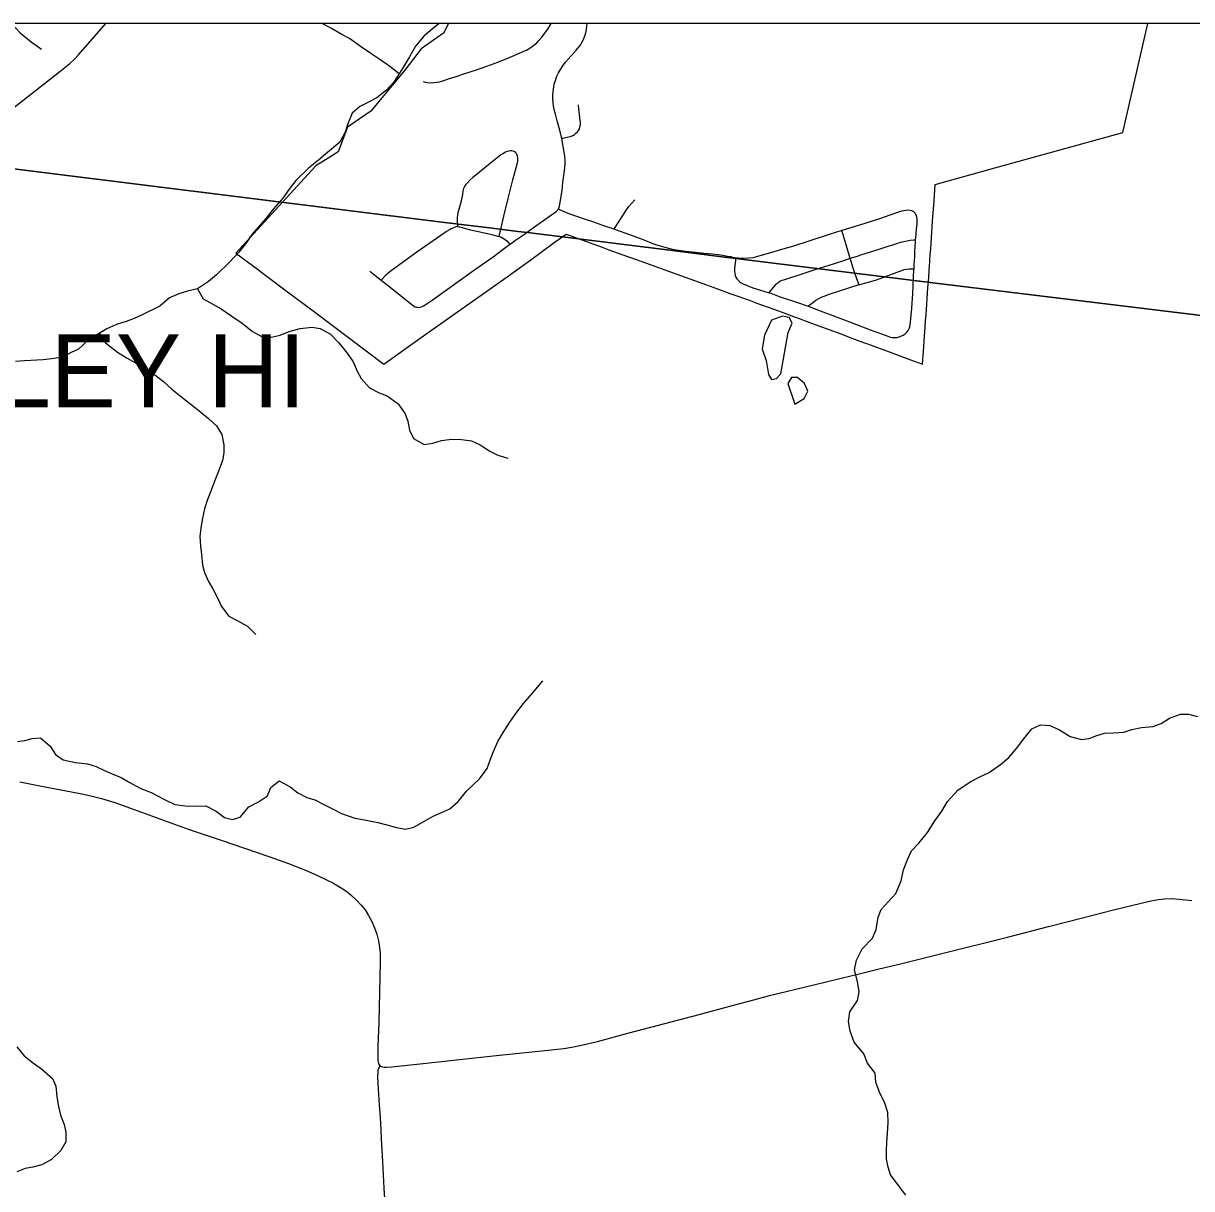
# Model space of a CAD drawing. Extents: x 0 to 1101, y 0 to 440.
# Drawn here: x 844.169 to 845.685, y 380.394 to 381.906 of the extents above; entities that cross this region are included whole.
import ezdxf

# ---------------------------------------------------------------- set-up
doc = ezdxf.new("R2010")
doc.units = 0
for name, color, linetype in [('GM_X_City_Street', 7, 'Continuous'), ('GM_X_Corporation', 7, 'Continuous'), ('GM_X_Corporation_Text', 7, 'Continuous'), ('GM_X_County_Road', 7, 'Continuous'), ('GM_X_Major_River', 7, 'Continuous'), ('GM_X_Minor_Lake', 7, 'Continuous'), ('GM_X_Minor_River', 7, 'Continuous'), ('SH_Cut_Line', 7, 'Continuous')]:
    doc.layers.add(name, color=color, linetype=linetype)

msp = doc.modelspace()

# ---------------------------------------------------------------- linework, layer by layer
at = {"layer": 'GM_X_City_Street'}
for points in [[(844.6879, 381.8304), (844.6906, 381.8296), (844.6933, 381.8292), (844.6975, 381.8289), (844.7017, 381.8291), (844.7054, 381.8295), (844.7089, 381.8302), (844.7131, 381.8315), (844.722, 381.8343), (844.7292, 381.8366), (844.7419, 381.8407), (844.7569, 381.8455), (844.7705, 381.8502), (844.7848, 381.8557), (844.8006, 381.8618), (844.8135, 381.8675), (844.8191, 381.8701), (844.8217, 381.8712), (844.824, 381.8725), (844.8279, 381.875), (844.8315, 381.8776), (844.835, 381.8808), (844.8383, 381.8841), (844.8417, 381.8881), (844.8453, 381.8927), (844.8493, 381.8984), (844.8526, 381.9037), (844.8537, 381.9059)], [(844.7784, 381.603), (844.7898, 381.6117), (844.7969, 381.6169), (844.8005, 381.6194), (844.8077, 381.6245), (844.8206, 381.6332), (844.8215, 381.6339), (844.8353, 381.6438), (844.8529, 381.6564), (844.8561, 381.6587), (844.8581, 381.6602), (844.8607, 381.6622), (844.8622, 381.6635), (844.8633, 381.6649), (844.8635, 381.6651), (844.8641, 381.6666), (844.8646, 381.6686), (844.865, 381.6714), (844.8679, 381.6892), (844.8689, 381.6993), (844.8705, 381.7117), (844.8714, 381.7189), (844.8719, 381.7238), (844.8719, 381.7284), (844.8715, 381.7335), (844.8708, 381.7388), (844.8677, 381.7563), (844.8676, 381.7566), (844.865, 381.7672), (844.8617, 381.7796), (844.8596, 381.788), (844.8579, 381.7939), (844.8568, 381.7989), (844.8562, 381.8024), (844.8558, 381.8078), (844.856, 381.8133), (844.8567, 381.8207), (844.8579, 381.8268), (844.8593, 381.8319), (844.8609, 381.8364), (844.8634, 381.8416), (844.8658, 381.846), (844.8689, 381.8509), (844.8722, 381.8554), (844.8758, 381.8596), (844.8796, 381.8637), (844.8862, 381.8709), (844.8889, 381.8741), (844.8917, 381.8778), (844.8937, 381.881), (844.8954, 381.8841), (844.8971, 381.8883), (844.8987, 381.8937), (844.8996, 381.8982), (844.9002, 381.9024), (844.9005, 381.9059)], [(844.8676, 381.7566), (844.869, 381.757), (844.8761, 381.7585), (844.8791, 381.7592), (844.8819, 381.7605), (844.8839, 381.7617), (844.886, 381.7633), (844.8879, 381.7651), (844.8893, 381.7669), (844.8904, 381.769), (844.8912, 381.7714), (844.8917, 381.7744), (844.8917, 381.7773), (844.8912, 381.7827), (844.8905, 381.7886), (844.8899, 381.7946), (844.8893, 381.8003)], [(844.7861, 381.6294), (844.7862, 381.6298), (844.7878, 381.6353), (844.7884, 381.6382), (844.7923, 381.6559), (844.7979, 381.6788), (844.804, 381.7029), (844.8101, 381.725), (844.8104, 381.7266), (844.8107, 381.7291), (844.8106, 381.7309), (844.8103, 381.7336), (844.8094, 381.7359), (844.8087, 381.7371), (844.8075, 381.7385), (844.8057, 381.7396), (844.804, 381.7402), (844.8022, 381.7404), (844.8006, 381.7404), (844.7987, 381.7401), (844.7968, 381.7396), (844.7944, 381.7387), (844.7909, 381.7367), (844.7884, 381.7351), (844.7856, 381.7328), (844.7772, 381.726), (844.7559, 381.7089), (844.7522, 381.7059), (844.7484, 381.7024), (844.7447, 381.6986), (844.7427, 381.6963), (844.7413, 381.694), (844.7402, 381.6914), (844.7394, 381.6883), (844.7389, 381.6844), (844.7382, 381.6812), (844.7376, 381.6783), (844.7369, 381.6751), (844.7336, 381.6632), (844.7329, 381.6599), (844.7323, 381.6569), (844.732, 381.6545), (844.7319, 381.651), (844.7318, 381.648), (844.7322, 381.6424), (844.735, 381.6418), (844.7379, 381.6411), (844.7426, 381.6399), (844.7493, 381.6381), (844.7634, 381.6349), (844.7769, 381.6318), (844.7861, 381.6294), (844.7883, 381.6287), (844.7906, 381.6276), (844.7928, 381.6263), (844.7944, 381.6251), (844.7961, 381.6237), (844.7995, 381.6203), (844.8005, 381.6194)], [(844.8633, 381.6649), (844.8648, 381.6642), (844.8754, 381.6598), (844.8867, 381.6555), (844.8978, 381.6518), (844.9073, 381.6486), (844.9218, 381.6437), (844.9338, 381.6395), (844.9358, 381.6388), (844.9556, 381.6318), (844.9717, 381.6257), (844.9739, 381.6248), (844.9864, 381.62), (844.9903, 381.6187), (844.9952, 381.617), (845.0013, 381.6153), (845.006, 381.614), (845.0116, 381.6128), (845.0159, 381.612), (845.028, 381.6103), (845.0411, 381.6089), (845.0517, 381.6078), (845.0631, 381.6066), (845.0705, 381.6058), (845.0767, 381.6049)], [(844.9358, 381.6388), (844.9362, 381.6395), (844.9485, 381.6593), (844.95, 381.6615), (844.9516, 381.6639), (844.9548, 381.6681), (844.9584, 381.6727), (844.9623, 381.677)], [(845.0767, 381.6049), (845.0828, 381.6039), (845.0863, 381.6032), (845.0907, 381.6022), (845.0936, 381.6015), (845.0922, 381.5918), (845.0918, 381.5876), (845.0918, 381.5844), (845.0921, 381.5817), (845.0926, 381.5789), (845.0935, 381.5766), (845.0949, 381.5744), (845.0963, 381.5725), (845.0982, 381.5707), (845.1002, 381.5693), (845.1029, 381.5678), (845.1156, 381.5628), (845.1256, 381.5596), (845.1366, 381.5564), (845.1387, 381.5558), (845.1497, 381.5516), (845.1735, 381.5435), (845.1858, 381.5392), (845.1871, 381.5388), (845.2027, 381.5329), (845.2282, 381.5232), (845.2498, 381.5153), (845.2678, 381.5084), (845.2826, 381.5028), (845.2905, 381.5), (845.2926, 381.4992), (845.294, 381.4988), (845.2961, 381.4983), (845.2981, 381.4981), (845.3005, 381.4981), (845.3029, 381.4984), (845.3054, 381.4991), (845.3076, 381.4999), (845.3106, 381.5014), (845.313, 381.5031), (845.3153, 381.5052), (845.3169, 381.5075), (845.3183, 381.51), (845.3191, 381.5122), (845.3196, 381.5149), (845.3201, 381.5183), (845.3219, 381.5361), (845.3229, 381.5553), (845.3245, 381.5863), (845.3246, 381.5876), (845.325, 381.594), (845.3251, 381.5972), (845.3255, 381.6036), (845.3258, 381.6098), (845.3261, 381.6165), (845.3264, 381.6221), (845.3266, 381.6248), (845.3269, 381.6276), (845.328, 381.6387), (845.3284, 381.6428), (845.3286, 381.6459), (845.3288, 381.6495), (845.3287, 381.6523), (845.3283, 381.6546), (845.3277, 381.6565), (845.3269, 381.658), (845.326, 381.6595), (845.3245, 381.6611), (845.3227, 381.6621), (845.32, 381.663), (845.3168, 381.6634), (845.314, 381.6632), (845.3112, 381.6627), (845.3084, 381.662), (845.3021, 381.66), (845.2784, 381.6519), (845.2526, 381.6434), (845.2311, 381.637), (845.2145, 381.6321), (845.1867, 381.6229), (845.1668, 381.6165), (845.1498, 381.6114), (845.1413, 381.6089), (845.1217, 381.6033), (845.1158, 381.6018), (845.1101, 381.6011), (845.104, 381.6009), (845.0998, 381.6008), (845.0964, 381.601), (845.0936, 381.6015)], [(844.7322, 381.6424), (844.7301, 381.6418), (844.7264, 381.6402), (844.724, 381.6391), (844.7218, 381.6378), (844.7189, 381.6361), (844.7161, 381.6344), (844.6797, 381.609), (844.6479, 381.5862), (844.6444, 381.5836), (844.6413, 381.5809), (844.6386, 381.5781), (844.6342, 381.5735), (844.6334, 381.5726), (844.6408, 381.5667), (844.6708, 381.5426), (844.6733, 381.5406), (844.6752, 381.5393), (844.6772, 381.5382), (844.6789, 381.5377), (844.6805, 381.5374), (844.6826, 381.5373), (844.6842, 381.5377), (844.6864, 381.5383), (844.6883, 381.5394), (844.6904, 381.5408), (844.6992, 381.5469), (844.7561, 381.5872), (844.7784, 381.603)], [(845.2534, 381.5669), (845.2531, 381.5676), (845.2498, 381.5757), (845.2458, 381.5881), (845.2418, 381.601), (845.2408, 381.6038), (845.2367, 381.6184), (845.2315, 381.6357), (845.2311, 381.637)], [(845.1366, 381.5564), (845.1377, 381.5576), (845.1436, 381.5648), (845.1456, 381.5673), (845.1466, 381.5684), (845.1478, 381.5693), (845.1494, 381.5704), (845.1515, 381.5716), (845.1537, 381.5725), (845.1569, 381.5737), (845.1797, 381.5809), (845.1978, 381.5868), (845.2203, 381.594), (845.2361, 381.5992), (845.2418, 381.601), (845.2512, 381.6039), (845.2558, 381.6054), (845.2805, 381.6131), (845.2912, 381.6166), (845.2985, 381.6191), (845.3022, 381.6203), (845.3072, 381.6218), (845.3115, 381.6229), (845.3157, 381.6238), (845.3198, 381.6244), (845.3245, 381.6248), (845.3266, 381.6248)], [(844.6187, 381.5842), (844.6252, 381.579), (844.6334, 381.5726)], [(845.1871, 381.5388), (845.1873, 381.539), (845.1932, 381.5438), (845.1974, 381.5467), (845.2012, 381.5488), (845.2056, 381.551), (845.2094, 381.5524), (845.2146, 381.5543), (845.2534, 381.5669), (845.2544, 381.5672), (845.2685, 381.571), (845.2759, 381.5731), (845.284, 381.5759), (845.291, 381.5786), (845.3061, 381.5843), (845.309, 381.5853), (845.312, 381.5863), (845.3149, 381.5869), (845.3182, 381.5873), (845.3236, 381.5875), (845.3246, 381.5876)]]:
    msp.add_lwpolyline(points, dxfattribs=at)
at = {"layer": 'GM_X_Corporation'}
msp.add_lwpolyline([(845.6282, 381.9059), (844.7207, 381.9059), (844.7139, 381.8932), (844.6853, 381.873), (844.6695, 381.8527), (844.6635, 381.8449), (844.6199, 381.792), (844.6197, 381.7918), (844.5897, 381.7713), (844.5775, 381.7392), (844.5702, 381.7346), (844.5484, 381.7209), (844.5053, 381.674), (844.4448, 381.6078), (844.466, 381.5919), (844.5082, 381.5603), (844.5467, 381.5314), (844.6368, 381.4638), (844.684, 381.4972), (844.7969, 381.5771), (844.8122, 381.5882), (844.8274, 381.5992), (844.8427, 381.6103), (844.8579, 381.6214), (844.8732, 381.6324), (844.8852, 381.628), (844.903, 381.6215), (844.9199, 381.6153), (844.9288, 381.612), (844.9467, 381.6056), (844.9641, 381.5993), (844.9821, 381.5928), (845.0059, 381.5842), (845.0231, 381.5781), (845.0396, 381.5721), (845.0552, 381.5665), (845.0698, 381.5613), (845.0869, 381.5551), (845.0975, 381.5513), (845.1048, 381.5487), (845.1121, 381.5461), (845.1184, 381.5438), (845.1194, 381.5434), (845.1267, 381.5408), (845.134, 381.5382), (845.1413, 381.5355), (845.1486, 381.5329), (845.1556, 381.5303), (845.1626, 381.5277), (845.1696, 381.5251), (845.1767, 381.5225), (845.1835, 381.5199), (845.1905, 381.5173), (845.1975, 381.5147), (845.2046, 381.5121), (845.2119, 381.5094), (845.219, 381.5068), (845.2262, 381.5041), (845.2332, 381.5015), (845.2404, 381.4988), (845.2474, 381.4962), (845.2544, 381.4936), (845.2618, 381.4909), (845.2689, 381.4882), (845.2759, 381.4856), (845.2832, 381.4829), (845.2902, 381.4803), (845.3214, 381.4687), (845.3358, 381.4637), (845.3369, 381.4801), (845.3383, 381.5001), (845.3392, 381.5127), (845.3397, 381.5199), (845.3402, 381.5271), (845.3403, 381.5283), (845.3407, 381.5343), (845.3412, 381.5414), (845.3417, 381.5486), (845.3422, 381.5558), (845.3427, 381.563), (845.3432, 381.5702), (845.3437, 381.5773), (845.3442, 381.5845), (845.3447, 381.5917), (845.345, 381.596), (845.3452, 381.5989), (845.3457, 381.6061), (845.3463, 381.6132), (845.3468, 381.6204), (845.3473, 381.6276), (845.3478, 381.6348), (845.3483, 381.642), (845.3488, 381.6491), (845.3506, 381.6757), (845.3521, 381.6969), (845.36, 381.6991), (845.4219, 381.7162), (845.5954, 381.7643)], close=True, dxfattribs=at)
at = {"layer": 'GM_X_County_Road'}
msp.add_lwpolyline([(847.9476, 381.9059), (842.3157, 381.9059), (843.023, 381.8481), (843.2462, 381.8298), (844.0658, 381.7282), (844.7118, 381.648), (844.7738, 381.6404), (844.8107, 381.6358), (844.8229, 381.6343), (845.008, 381.6114), (845.0655, 381.6042), (845.3492, 381.569), (845.7047, 381.5258), (845.7218, 381.5239), (845.8327, 381.5116), (846.7534, 381.4335), (846.7617, 381.4329), (846.7789, 381.4314), (846.8323, 381.427), (847.896, 381.3391), (847.9127, 381.5179)], close=True, dxfattribs=at)
for points in [[(844.0691, 381.7292), (844.1069, 381.7581), (844.1681, 381.8059), (844.2162, 381.8433), (844.2228, 381.8484), (844.2292, 381.8538), (844.2348, 381.8592), (844.2406, 381.865), (844.2644, 381.8921), (844.2761, 381.9059)], [(847.5335, 377.0456), (847.6089, 377.9284), (847.6897, 378.8763), (847.7828, 379.9871), (847.8653, 380.9722), (847.896, 381.3391), (846.8323, 381.427), (846.7789, 381.4314), (846.7617, 381.4329), (846.7534, 381.4335), (845.8327, 381.5116), (845.7218, 381.5239), (845.7047, 381.5258), (845.3492, 381.569), (845.0655, 381.6042), (845.008, 381.6114), (844.8229, 381.6343), (844.8107, 381.6358), (844.7738, 381.6404), (844.7118, 381.648), (844.0658, 381.7282)], [(844.1643, 380.9218), (844.1905, 380.9164), (844.2404, 380.9068), (844.2492, 380.9052), (844.2618, 380.9024), (844.2704, 380.9002), (844.2876, 380.8947), (844.3128, 380.8859), (844.3556, 380.87), (844.384, 380.86), (844.4257, 380.8459), (844.4873, 380.8247), (844.513, 380.8155), (844.5349, 380.8069), (844.5498, 380.8006), (844.5633, 380.7942), (844.5705, 380.7904), (844.5812, 380.7841), (844.5885, 380.7793), (844.5949, 380.7743), (844.6009, 380.7687), (844.6073, 380.7618), (844.6123, 380.7554), (844.617, 380.748), (844.6212, 380.7403), (844.6247, 380.7322), (844.6275, 380.724), (844.6297, 380.7155), (844.6312, 380.7068), (844.6319, 380.6993), (844.6321, 380.6875), (844.6304, 380.6098), (844.6291, 380.5781), (844.6288, 380.5651), (844.629, 380.5596), (844.6294, 380.5579), (844.6299, 380.5562), (844.6303, 380.5553), (844.6311, 380.5542), (844.6316, 380.5537), (844.6323, 380.5532), (844.6336, 380.5523), (844.6354, 380.5517), (844.6376, 380.5514), (844.6403, 380.5514), (844.6471, 380.5519), (844.6879, 380.5563), (844.7194, 380.5598), (844.7787, 380.5661), (844.8498, 380.5734), (844.8701, 380.5758), (844.883, 380.5779), (844.8969, 380.5807), (844.9138, 380.5848), (844.9551, 380.5961), (845.0458, 380.6197), (845.0903, 380.6318), (845.1167, 380.6389), (845.1371, 380.6442), (845.1945, 380.6582), (845.2301, 380.6669), (845.2516, 380.6722), (845.2776, 380.6785), (845.309, 380.6861), (845.3608, 380.6987), (845.4461, 380.7203), (845.4992, 380.7339), (845.5431, 380.7451), (845.5834, 380.7554), (845.6069, 380.7613), (845.6317, 380.7672), (845.6415, 380.7691), (845.6496, 380.77), (845.6584, 380.7702), (845.669, 380.7696), (845.6851, 380.7678)], [(844.6405, 380.3405), (844.6372, 380.3945), (844.6353, 380.4292), (844.6338, 380.4583), (844.6331, 380.4695), (844.6322, 380.4863), (844.631, 380.5024), (844.6293, 380.5302), (844.629, 380.5393), (844.6292, 380.545), (844.6294, 380.5471), (844.6297, 380.5487), (844.6309, 380.552), (844.6316, 380.5537)]]:
    msp.add_lwpolyline(points, dxfattribs=at)
at = {"layer": 'GM_X_Major_River'}
msp.add_lwpolyline([(844.7084, 381.9059), (844.6996, 381.8983), (844.6889, 381.8897), (844.6777, 381.8762), (844.6699, 381.8626), (844.6637, 381.8517), (844.6571, 381.8412), (844.6494, 381.8291), (844.6402, 381.819), (844.6275, 381.8093), (844.6161, 381.8034), (844.6054, 381.7982), (844.5954, 381.7893), (844.5899, 381.7753), (844.5864, 381.7647), (844.5794, 381.7519), (844.5636, 381.7381), (844.5521, 381.7284), (844.5391, 381.7179), (844.5226, 381.7018), (844.5137, 381.6909), (844.5056, 381.6789), (844.4937, 381.6654), (844.4837, 381.6526), (844.4659, 381.6324), (844.4571, 381.6196), (844.4486, 381.6091), (844.4366, 381.5959), (844.4197, 381.5795), (844.409, 381.5709), (844.3949, 381.5612), (844.3819, 381.5583), (844.3705, 381.5551), (844.3587, 381.5496), (844.3461, 381.5387), (844.3224, 381.5273), (844.3129, 381.5228), (844.3022, 381.5188), (844.29, 381.5152), (844.2774, 381.5093), (844.2641, 381.5019), (844.2534, 381.4952), (844.2407, 381.4832), (844.2312, 381.4788), (844.2201, 381.4729), (844.2057, 381.4704), (844.1947, 381.4691), (844.1704, 381.4679), (844.1586, 381.4673)], dxfattribs=at)
at = {"layer": 'GM_X_Minor_Lake'}
for points in [[(845.1615, 381.5047), (845.1666, 381.5168), (845.1626, 381.524), (845.1539, 381.5261), (845.1398, 381.5209), (845.1308, 381.5013), (845.1275, 381.4835), (845.1326, 381.4683), (845.1358, 381.4504), (845.1399, 381.4439), (845.146, 381.4449), (845.1517, 381.4509)], [(845.1517, 381.4509), (845.1615, 381.5047)], [(845.1698, 381.4119), (845.182, 381.419), (845.1867, 381.4284), (845.1826, 381.4387), (845.1736, 381.4464), (845.1657, 381.4465), (845.1607, 381.4386)], [(845.1607, 381.4386), (845.1698, 381.4119)]]:
    msp.add_lwpolyline(points, dxfattribs=at)
at = {"layer": 'GM_X_Minor_River'}
for points in [[(844.1535, 381.9059), (844.1536, 381.9058), (844.1648, 381.8935), (844.179, 381.8819), (844.1925, 381.8726)], [(844.6566, 381.8404), (844.6444, 381.8497), (844.6301, 381.8598), (844.62, 381.8667), (844.6076, 381.8749), (844.5922, 381.8861), (844.5824, 381.8916), (844.5689, 381.8993), (844.5591, 381.9044), (844.5567, 381.9059)], [(844.3949, 381.5612), (844.4023, 381.5486), (844.4158, 381.5412), (844.4256, 381.5353), (844.4395, 381.526), (844.453, 381.5167), (844.4661, 381.5059), (844.4789, 381.4993), (844.491, 381.4988), (844.5021, 381.5013), (844.5139, 381.506), (844.5283, 381.51), (844.5435, 381.5117), (844.5541, 381.51), (844.5673, 381.5026), (844.5781, 381.4915), (844.5889, 381.4781), (844.5967, 381.4666), (844.6019, 381.4547), (844.6074, 381.4451), (844.6179, 381.4329), (844.6307, 381.4266), (844.6412, 381.4227), (844.6551, 381.4122), (844.6644, 381.3992), (844.6677, 381.3897), (844.6702, 381.3782), (844.675, 381.3672), (844.6889, 381.3594), (844.7003, 381.3611), (844.7117, 381.3644), (844.7216, 381.3661), (844.7344, 381.3663), (844.7503, 381.3642), (844.7616, 381.3591), (844.7744, 381.3506), (844.7846, 381.3455), (844.7974, 381.3416)], [(844.2676, 381.5039), (844.2757, 381.4915), (844.2911, 381.4791), (844.3035, 381.4713), (844.3144, 381.4655), (844.3275, 381.4577), (844.3395, 381.45), (844.3508, 381.4411), (844.3617, 381.4314), (844.3766, 381.4191), (844.3883, 381.4102), (844.3991, 381.4013), (844.4093, 381.3932), (844.4194, 381.3836), (844.4264, 381.3725), (844.4293, 381.3588), (844.4291, 381.3485), (844.4275, 381.3387), (844.4216, 381.3236), (844.4176, 381.3126), (844.4122, 381.299), (844.4078, 381.2881), (844.4039, 381.276), (844.4014, 381.2639), (844.3998, 381.254), (844.3981, 381.2404), (844.3987, 381.2275), (844.4, 381.2168), (844.4014, 381.2027), (844.4039, 381.1932), (844.4094, 381.1818), (844.415, 381.1722), (844.4202, 381.1622), (844.426, 381.1493), (844.4357, 381.1366), (844.4466, 381.1311), (844.4598, 381.1237), (844.4706, 381.113)], [(844.8003, 380.9991), (844.8081, 381.0104), (844.8181, 381.0232), (844.8296, 381.0367), (844.8431, 381.0528)], [(844.1614, 380.9741), (844.1709, 380.9751), (844.1804, 380.978), (844.191, 380.9786), (844.2038, 380.9678), (844.2108, 380.9571), (844.2206, 380.9501), (844.2368, 380.9469), (844.2523, 380.9451), (844.2633, 380.9416), (844.2742, 380.9365), (844.284, 380.9322), (844.2957, 380.9271), (844.3055, 380.9216), (844.3213, 380.9131), (844.3348, 380.9079), (844.3521, 380.8986), (844.3657, 380.8923), (844.3789, 380.8903), (844.3933, 380.8901), (844.4058, 380.8903), (844.419, 380.8836), (844.4299, 380.8755), (844.4405, 380.8727), (844.4504, 380.876), (844.4615, 380.8891), (844.4741, 380.8958), (844.4856, 380.9036), (844.4899, 380.9142), (844.501, 380.9231), (844.5153, 380.9153), (844.5251, 380.9076), (844.5367, 380.9014), (844.5473, 380.8982), (844.559, 380.8923), (844.5703, 380.8865), (844.5819, 380.8806), (844.5989, 380.8747), (844.6117, 380.8723), (844.6288, 380.869), (844.6405, 380.8658), (844.6533, 380.8622), (844.665, 380.8601), (844.6757, 380.863), (844.6886, 380.8701), (844.7005, 380.8771), (844.7108, 380.8815), (844.7222, 380.8867), (844.7333, 380.896), (844.7441, 380.9095), (844.7607, 380.9256), (844.7707, 380.9388), (844.775, 380.9509), (844.779, 380.9611), (844.7848, 380.9739), (844.7922, 380.9871), (844.8003, 380.9991)], [(845.3141, 380.3855), (845.3048, 380.3974), (845.294, 380.4116), (845.2911, 380.4215), (845.289, 380.4325), (845.2888, 380.4428), (845.2893, 380.4541), (845.2902, 380.4655), (845.2912, 380.4795), (845.2906, 380.4925), (845.2862, 380.5058), (845.2803, 380.5176), (845.2752, 380.5321), (845.2743, 380.5435), (845.2642, 380.5566), (845.2594, 380.5688), (845.2468, 380.5838), (845.2417, 380.5983), (845.2396, 380.6108), (845.2412, 380.6233), (845.2513, 380.638), (845.2534, 380.6493), (845.2513, 380.6626), (845.2473, 380.6775), (845.2501, 380.6904), (845.2572, 380.7051), (845.2706, 380.7189), (845.2753, 380.7299), (845.2782, 380.7462), (845.2821, 380.756), (845.2917, 380.7665), (845.301, 380.7766), (845.308, 380.7932), (845.3109, 380.8076), (845.3164, 380.8219), (845.3214, 380.8321), (845.3307, 380.8422), (845.3422, 380.8557), (845.3515, 380.8711), (845.3608, 380.8835), (845.3682, 380.896), (845.3816, 380.911), (845.3973, 380.9217), (845.4099, 380.928), (845.4221, 380.9339), (845.437, 380.944), (845.4478, 380.9533), (845.4574, 380.9649), (845.4671, 380.9773), (845.4775, 380.9905), (845.4889, 380.9956), (845.5007, 380.9947), (845.5135, 380.9892), (845.5274, 380.9807), (845.5421, 380.9767), (845.552, 380.9777), (845.5619, 380.9817), (845.5718, 380.9846), (845.5835, 380.9852), (845.5968, 380.9861), (845.6071, 380.9894), (845.62, 380.9923), (845.6344, 380.9936), (845.6455, 380.9972), (845.6562, 381.0043), (845.6703, 381.0094), (845.6809, 381.0096), (845.6926, 381.0064)], [(844.1605, 380.5778), (844.1702, 380.5663), (844.1822, 380.5566), (844.1927, 380.5493), (844.2066, 380.5366), (844.2113, 380.5266), (844.2123, 380.513), (844.2144, 380.5004), (844.2173, 380.489), (844.222, 380.4768), (844.2242, 380.4665), (844.224, 380.4543), (844.2178, 380.4434), (844.2055, 380.4314), (844.1929, 380.4248), (844.1811, 380.4215), (844.1712, 380.4198), (844.1605, 380.4154)]]:
    msp.add_lwpolyline(points, dxfattribs=at)
at = {"layer": 'SH_Cut_Line'}
msp.add_lwpolyline([(843.7743, 376.6401), (844.4941, 376.5699), (845.4182, 376.4736), (845.5612, 376.461), (845.6523, 376.4464), (845.8289, 376.4273), (846.6778, 376.3437), (847.4662, 376.2566), (847.7946, 376.221), (849.0627, 376.0925), (849.9034, 375.9956), (850.1463, 375.9688), (850.9258, 375.8797), (850.9258, 381.9059), (837.3258, 381.9059)], dxfattribs=at)

# ---------------------------------------------------------------- texts
at = {"layer": 'GM_X_Corporation_Text'}
msp.add_text('VALLEY HI', height=0.0947, rotation=0, dxfattribs=at).set_placement((843.8948, 381.4076))

doc.saveas('drawing.dxf')
